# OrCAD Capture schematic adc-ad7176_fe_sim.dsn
size A2
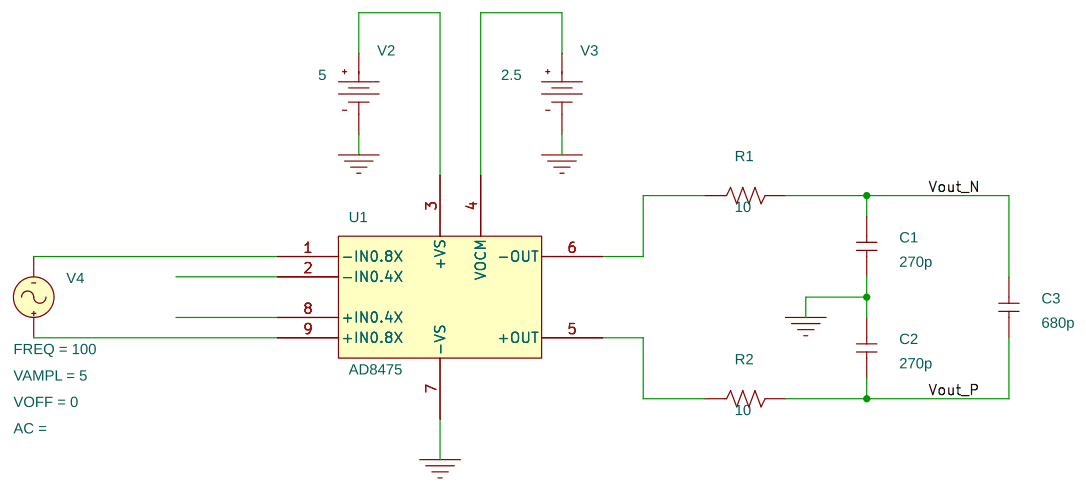
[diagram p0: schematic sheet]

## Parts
C1  270p  [cap196]
C2  270p  [cap196]
C3  680p  [cap196]
R1  10  [AXRC05]
R2  10  [AXRC05]
U1  AD8475
V2  VDC
V3  VDC
V4  VSIN

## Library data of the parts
C1-C3 = C
R1 R2 = R
U1 = AD8475_1
V2 = VDC: DC: 5
V3 = VDC: DC: 2.5
V4 = VSIN: FREQ: 100; VAMPL: 5; VOFF: 0

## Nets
0: C1.1 C2.2 U1.7(-VS) V2.1(-) V3.1(-)
Vout_N: C1.2 C3.2 R1.2
Vout_P: C2.1 C3.1 R2.2
N00592: U1.3(+VS) V2.0(+)
N00605: U1.4(VOCM) V3.0(+)
N00644: R1.1 U1.6(-OUT)
N00663: R2.1 U1.5(+OUT)
N01261: U1.1(-IN0.8X) V4.2(-)
N01265: U1.9(+IN0.8X) V4.1(+)

Not connected (* = marked no-connect by the designer): U1 2(-IN0.4X) 8(+IN0.4X)
